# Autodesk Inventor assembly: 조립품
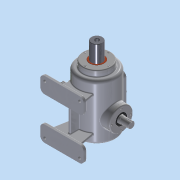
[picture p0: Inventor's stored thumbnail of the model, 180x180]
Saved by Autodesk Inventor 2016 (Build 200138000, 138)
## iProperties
Created: 2018-11
Part Number: 조립품
Material: 일반
Document SubType Name: Assembly
Designer: 공506_41
Mass: 8191.27 g
Surface Area: 4241.81 cm^2
Volume: 1855.49 cm^3
Density: 4.41462 g/cm^3
Author: 공506_41
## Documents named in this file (15)
- C:\Users\공506_41\Desktop\새 폴더 (2)\381121V1006\조립품.iam
- C:\Users\공506_41\Desktop\새 폴더 (2)\381121V1006\가변스프링.ipt
- C:\Users\공506_41\Desktop\새 폴더 (2)\381121V1006\베어링 6205.ipt
- 베어링 6205.ipt
- C:\Users\공506_41\Desktop\새 폴더 (2)\381121V1006\본체.ipt
- C:\Users\공506_41\Desktop\새 폴더 (2)\381121V1006\볼트 M4x0.7.ipt
- C:\Users\공506_41\Desktop\새 폴더 (2)\381121V1006\부시.ipt
- C:\Users\공506_41\Desktop\새 폴더 (2)\381121V1006\상부커버.ipt
- C:\Users\공506_41\Desktop\새 폴더 (2)\381121V1006\슬라이드 커버.ipt
- C:\Users\공506_41\Desktop\새 폴더 (2)\381121V1006\슬라이드.ipt
- C:\Users\공506_41\Desktop\새 폴더 (2)\381121V1006\오일실.ipt
- 오일실.ipt
- C:\Users\공506_41\Desktop\새 폴더 (2)\381121V1006\육각머리볼트 M4.ipt
- C:\Users\공506_41\Desktop\새 폴더 (2)\381121V1006\축 커버.ipt
- C:\Users\공506_41\Desktop\새 폴더 (2)\381121V1006\편심축.ipt
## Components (13 placed, 2 different names)
1. 가변스프링:1
2. M4x0.7:2
3. M4x0.7:4
4. M4x0.7:5
5. M4x0.7:6
6. M4x0.7:1
7. M4x0.7:7
8. M4x0.7:8
9. M4x0.7:9
10. M4x0.7:3
11. M4x0.7:10
12. M4x0.7:11
13. M4x0.7:12
